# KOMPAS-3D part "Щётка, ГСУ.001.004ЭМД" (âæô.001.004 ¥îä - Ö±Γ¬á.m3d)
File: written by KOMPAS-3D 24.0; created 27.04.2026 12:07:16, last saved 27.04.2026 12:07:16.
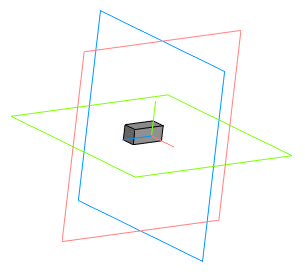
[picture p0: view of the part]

Document properties: Автор: USG_411; Полное имя файла: C:\Users\USG_411.STUD\Desktop\ГМ2704_411-23\Двигатель мясорубки\ГСУ.001.004 ЭМД - Щётка.m3d

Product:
- Part/product: Щётка  | designation ГСУ.001.004ЭМД
    Масса: 0.001131

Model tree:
1. Параллелепипед:1
     Длина = 4; Ширина = 4; Расстояние 1 = 9

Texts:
  ГСУ.001.004
  ГСУ.001.004 ЭМД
